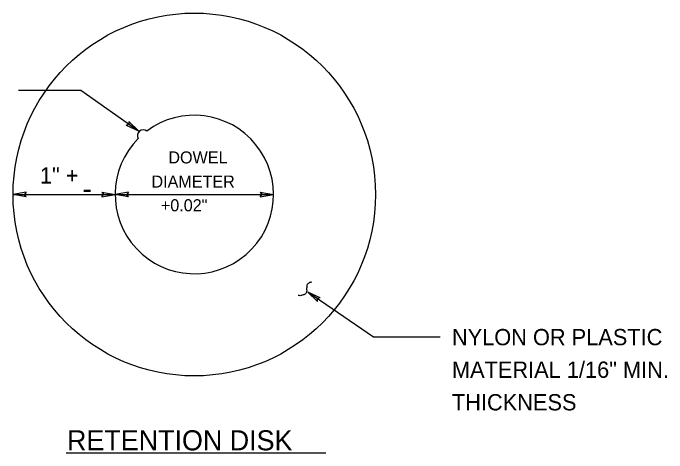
# Model space of a CAD drawing. Extents: x 2.92 to 10.05, y 1.3 to 10.63.
# Drawn here: x 5.153 to 8.407, y 8.441 to 10.627 of the extents above; entities that cross this region are included whole.
import ezdxf

# ---------------------------------------------------------------- set-up
doc = ezdxf.new("R2010")
doc.units = 0
for name, color, linetype in [('DETL-DIMS', 7, 'Continuous'), ('DETL-LINE', 7, 'Continuous'), ('DETL-NOTE', 7, 'Continuous'), ('DETL-TITL', 7, 'Continuous')]:
    doc.layers.add(name, color=color, linetype=linetype)

msp = doc.modelspace()

# ---------------------------------------------------------------- linework, layer by layer
at = {"layer": 'DETL-DIMS'}
for p, q in [((5.1807, 10.2436), (5.49, 10.2436)), ((5.49, 10.2436), (5.7768, 10.0419)), ((5.7292, 10.0888), (5.7768, 10.0419)), ((5.7292, 10.0888), (5.7297, 10.0751)), ((5.7166, 10.0708), (5.7297, 10.0751)), ((5.7166, 10.0708), (5.7768, 10.0419)), ((5.219, 9.7364), (5.1531, 9.7255)), ((5.219, 9.7364), (5.2108, 9.7255)), ((5.5951, 9.7365), (5.6609, 9.7255)), ((5.5951, 9.7365), (5.6032, 9.7255)), ((5.7269, 9.7364), (5.661, 9.7255)), ((5.7269, 9.7364), (5.7187, 9.7255)), ((6.3834, 9.7365), (6.4492, 9.7255)), ((6.3834, 9.7365), (6.3916, 9.7255)), ((5.219, 9.7145), (5.1531, 9.7255)), ((5.1531, 9.7255), (5.6609, 9.7255)), ((5.219, 9.7145), (5.2108, 9.7255)), ((5.595, 9.7145), (5.6609, 9.7255)), ((5.595, 9.7145), (5.6032, 9.7255)), ((5.7269, 9.7145), (5.661, 9.7255)), ((5.661, 9.7255), (6.4492, 9.7255)), ((5.7269, 9.7145), (5.7187, 9.7255)), ((6.3833, 9.7145), (6.4492, 9.7255)), ((6.3833, 9.7145), (6.3916, 9.7255)), ((6.9464, 9.0165), (6.6204, 9.2406)), ((6.6685, 9.1943), (6.6204, 9.2406)), ((6.6809, 9.2124), (6.6204, 9.2406)), ((6.6809, 9.2124), (6.6679, 9.208)), ((6.6685, 9.1943), (6.6679, 9.208)), ((7.2784, 9.0165), (6.9464, 9.0165))]:
    msp.add_line(p, q, dxfattribs=at)
msp.add_spline([(6.6398, 9.2882), (6.6349, 9.2892), (6.6307, 9.288), (6.6263, 9.2869), (6.6227, 9.2836), (6.6189, 9.2803), (6.6158, 9.2749), (6.6152, 9.2644), (6.6142, 9.2595), (6.6143, 9.2504), (6.6121, 9.2371), (6.609, 9.2316), (6.6039, 9.2291), (6.5967, 9.226), (6.5881, 9.2238), (6.5817, 9.222), (6.5733, 9.2233), (6.5712, 9.2227)], degree=3, dxfattribs=at)
at = {"layer": 'DETL-LINE'}
msp.add_circle((6.0551, 9.7255), 0.902, dxfattribs=at)
for centre, radius, start, end in [((6.0551, 9.7255), 0.3941, 135, 126.8699), ((5.8005, 10.0191), 0.0283, 50.0822, 211.8357)]:
    msp.add_arc(centre, radius, start, end, dxfattribs=at)
at = {"layer": 'DETL-TITL'}
msp.add_line((5.4172, 8.4407), (6.7088, 8.4407), dxfattribs=at)

# ---------------------------------------------------------------- texts
at = {"layer": 'DETL-NOTE'}
for s, height, p in [('DOWEL', 0.06, (5.926, 9.8799)), ('1" +', 0.081, (5.2869, 9.78)), ('DIAMETER', 0.06, (5.842, 9.7599)), ('-', 0.1094, (5.4972, 9.7017)), ('+0.02"', 0.06, (5.8887, 9.642))]:
    msp.add_text(s, height=height, rotation=360, dxfattribs=at).set_placement(p)
for s, p in [('NYLON OR PLASTIC', (7.3372, 8.976)), ('MATERIAL 1/16" MIN.', (7.3372, 8.814)), ('THICKNESS', (7.3372, 8.652))]:
    msp.add_text(s, height=0.081, dxfattribs=at).set_placement(p)
at = {"layer": 'DETL-TITL'}
msp.add_text('RETENTION DISK', height=0.1, dxfattribs=at).set_placement((5.4217, 8.4533))

doc.saveas('drawing.dxf')
